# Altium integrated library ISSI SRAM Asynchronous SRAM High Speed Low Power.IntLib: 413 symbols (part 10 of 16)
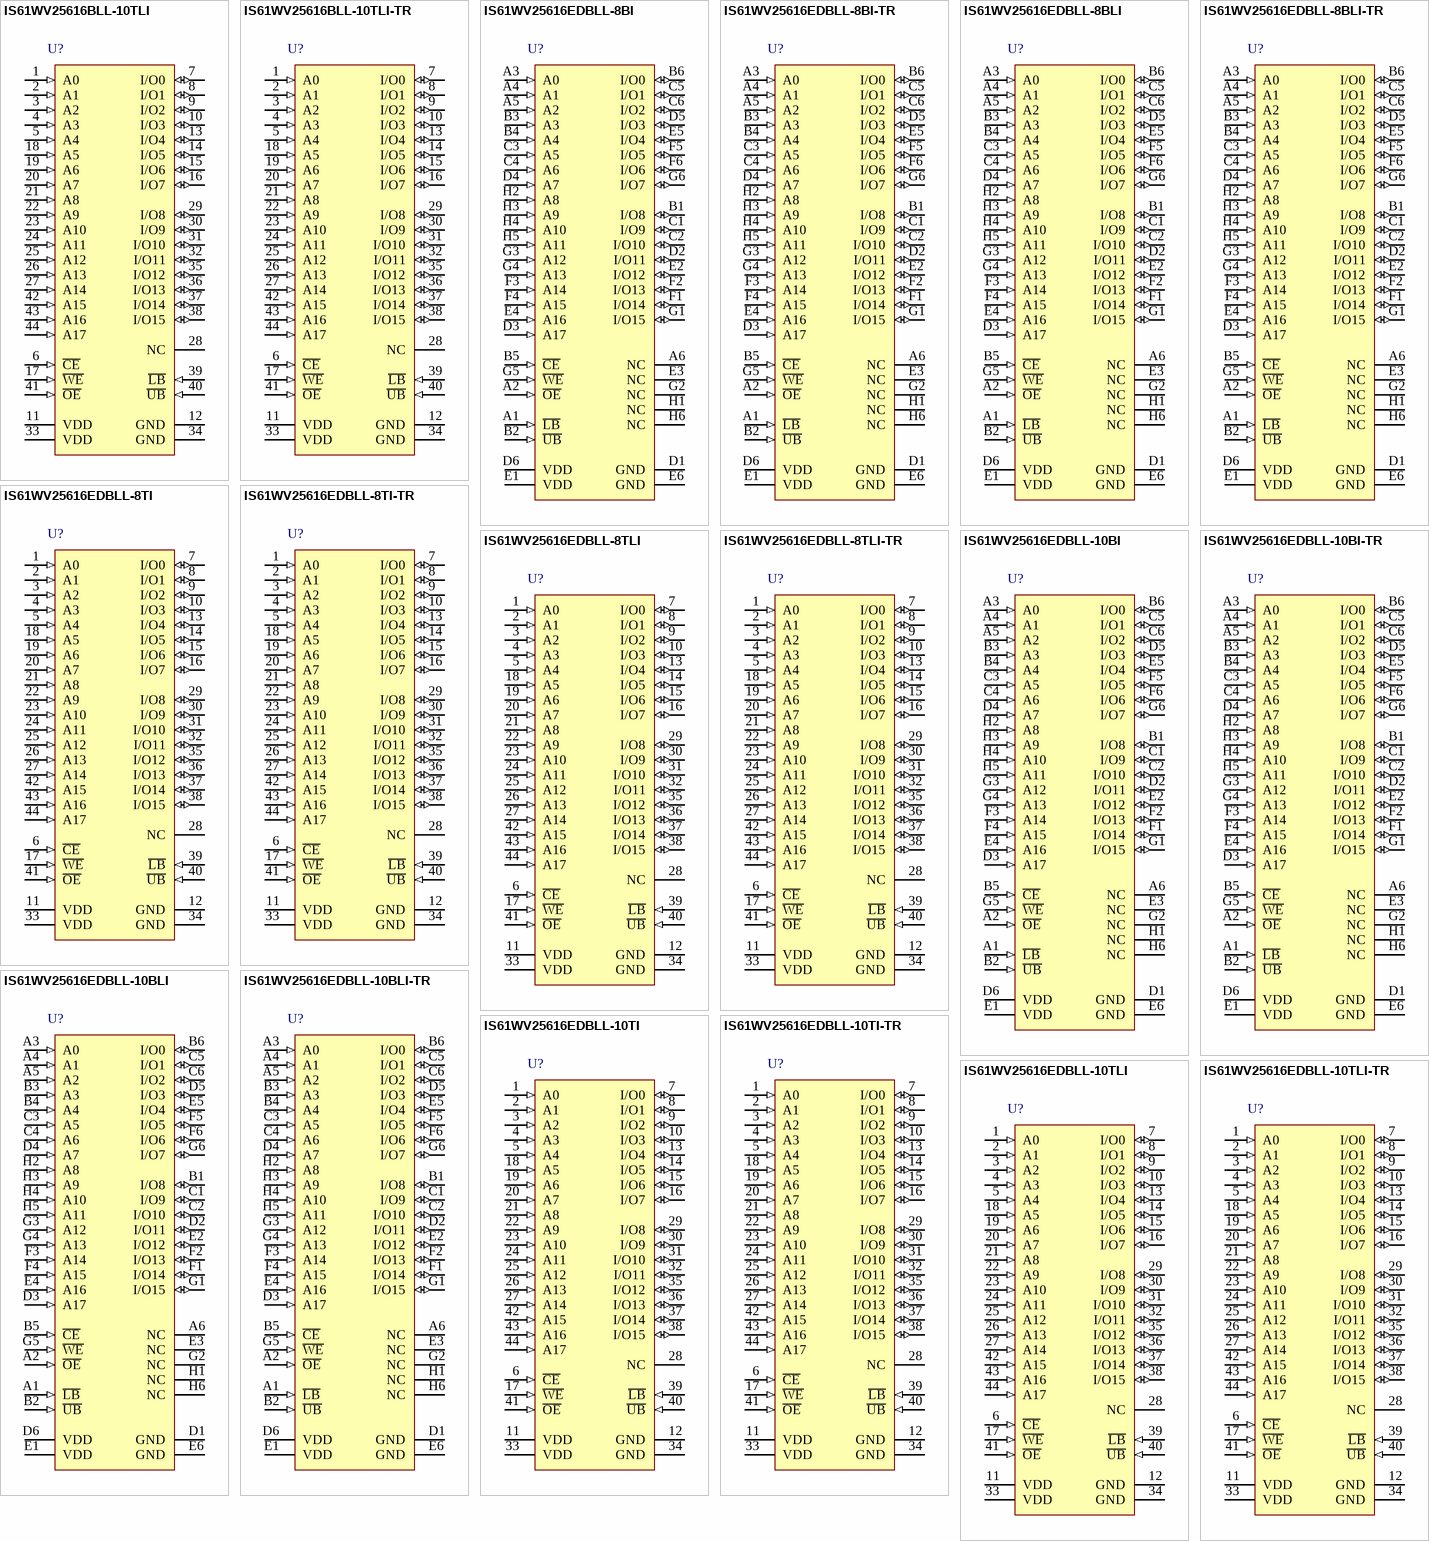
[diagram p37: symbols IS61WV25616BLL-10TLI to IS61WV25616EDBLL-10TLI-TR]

## IS61WV25616EDBLL-8BLI-TR
designator U?
4 M High Speed Asynchronous CMOS SRAM with ECC, 256 K x 16, -40 to 85 degC, 48-Pin BGA (TF-BGA-48), Pb-Free; Manufacturer: Integrated Silicon Solution Inc (ISSI); PartNumber: IS61WV25616EDBLL-8BLI-TR; Density: 4M; Packing: Tape & Reel; Speed (ns): 8
footprint ISSI-TF-BGA-48-6000X8000DE (BGA, 48-Balls, Body 8x6mm, Pitch 0.75mm)
pins: A1 ~{LB} (in) "Lower-byte Control (I/O0-I/O7)", A2 ~{OE} (in) "Output Enable Input", A3 A0 (in) "Address Input", A4 A1 (in) "Address Input", A5 A2 (in) "Address Input", A6 NC "No Connection", B1 I/O8 (io) "Data Input/Output", B2 ~{UB} (in) "Upper-byte Control (I/O8-I/O15)", B3 A3 (in) "Address Input", B4 A4 (in) "Address Input", B5 ~{CE} (in) "Chip Enable Input", B6 I/O0 (io) "Data Input/Output", C1 I/O9 (io) "Data Input/Output", C2 I/O10 (io) "Data Input/Output", C3 A5 (in) "Address Input", C4 A6 (in) "Address Input", C5 I/O1 (io) "Data Input/Output", C6 I/O2 (io) "Data Input/Output", D1 GND (power) "Ground", D2 I/O11 (io) "Data Input/Output", D3 A17 (in) "Address Input", D4 A7 (in) "Address Input", D5 I/O3 (io) "Data Input/Output", D6 VDD (power) "Power", E1 VDD (power) "Power", E2 I/O12 (io) "Data Input/Output", E3 NC "No Connection", E4 A16 (in) "Address Input", E5 I/O4 (io) "Data Input/Output", E6 GND (power) "Ground", F1 I/O14 (io) "Data Input/Output", F2 I/O13 (io) "Data Input/Output", F3 A14 (in) "Address Input", F4 A15 (in) "Address Input", F5 I/O5 (io) "Data Input/Output", F6 I/O6 (io) "Data Input/Output", G1 I/O15 (io) "Data Input/Output", G2 NC "No Connection", G3 A12 (in) "Address Input", G4 A13 (in) "Address Input", G5 ~{WE} (in) "Write Enable Input", G6 I/O7 (io) "Data Input/Output", H1 NC "No Connection", H2 A8 (in) "Address Input", H3 A9 (in) "Address Input", H4 A10 (in) "Address Input", H5 A11 (in) "Address Input", H6 NC "No Connection"

## IS61WV25616EDBLL-8TI
designator U?
4 M High Speed Asynchronous CMOS SRAM with ECC, 256 K x 16, -40 to 85 degC, 44-Pin SOP (TSOP-2-44); Manufacturer: Integrated Silicon Solution Inc (ISSI); PartNumber: IS61WV25616EDBLL-8TI; Density: 4M; Packing: Tray / Tube; Speed (ns): 8
footprint ISSI-TSOP-2-44_N (SOP, 44-Leads, Body 18.5x10.3mm, Pitch 0.8mm, IPC Medium Density)
pins: 1 A0 (in) "Address Input", 2 A1 (in) "Address Input", 3 A2 (in) "Address Input", 4 A3 (in) "Address Input", 5 A4 (in) "Address Input", 6 ~{CE} (in) "Chip Enable Input", 7 I/O0 (io) "Data Input/Output", 8 I/O1 (io) "Data Input/Output", 9 I/O2 (io) "Data Input/Output", 10 I/O3 (io) "Data Input/Output", 11 VDD (power) "Power", 12 GND (power) "Ground", 13 I/O4 (io) "Data Input/Output", 14 I/O5 (io) "Data Input/Output", 15 I/O6 (io) "Data Input/Output", 16 I/O7 (io) "Data Input/Output", 17 ~{WE} (in) "Write Enable Input", 18 A5 (in) "Address Input", 19 A6 (in) "Address Input", 20 A7 (in) "Address Input", 21 A8 (in) "Address Input", 22 A9 (in) "Address Input", 23 A10 (in) "Address Input", 24 A11 (in) "Address Input", 25 A12 (in) "Address Input", 26 A13 (in) "Address Input", 27 A14 (in) "Address Input", 28 NC "No Connection", 29 I/O8 (io) "Data Input/Output", 30 I/O9 (io) "Data Input/Output", 31 I/O10 (io) "Data Input/Output", 32 I/O11 (io) "Data Input/Output", 33 VDD (power) "Power", 34 GND (power) "Ground", 35 I/O12 (io) "Data Input/Output", 36 I/O13 (io) "Data Input/Output", 37 I/O14 (io) "Data Input/Output", 38 I/O15 (io) "Data Input/Output", 39 ~{LB} (in) "Lower-byte Control (I/O0-I/O7)", 40 ~{UB} (in) "Upper-byte Control (I/O8-I/O15)", 41 ~{OE} (in) "Output Enable Input", 42 A15 (in) "Address Input", 43 A16 (in) "Address Input", 44 A17 (in) "Address Input"

## IS61WV25616EDBLL-8TI-TR
designator U?
4 M High Speed Asynchronous CMOS SRAM with ECC, 256 K x 16, -40 to 85 degC, 44-Pin SOP (TSOP-2-44); Manufacturer: Integrated Silicon Solution Inc (ISSI); PartNumber: IS61WV25616EDBLL-8TI-TR; Density: 4M; Packing: Tape & Reel; Speed (ns): 8
footprint ISSI-TSOP-2-44_N (SOP, 44-Leads, Body 18.5x10.3mm, Pitch 0.8mm, IPC Medium Density)
pins: 1 A0 (in) "Address Input", 2 A1 (in) "Address Input", 3 A2 (in) "Address Input", 4 A3 (in) "Address Input", 5 A4 (in) "Address Input", 6 ~{CE} (in) "Chip Enable Input", 7 I/O0 (io) "Data Input/Output", 8 I/O1 (io) "Data Input/Output", 9 I/O2 (io) "Data Input/Output", 10 I/O3 (io) "Data Input/Output", 11 VDD (power) "Power", 12 GND (power) "Ground", 13 I/O4 (io) "Data Input/Output", 14 I/O5 (io) "Data Input/Output", 15 I/O6 (io) "Data Input/Output", 16 I/O7 (io) "Data Input/Output", 17 ~{WE} (in) "Write Enable Input", 18 A5 (in) "Address Input", 19 A6 (in) "Address Input", 20 A7 (in) "Address Input", 21 A8 (in) "Address Input", 22 A9 (in) "Address Input", 23 A10 (in) "Address Input", 24 A11 (in) "Address Input", 25 A12 (in) "Address Input", 26 A13 (in) "Address Input", 27 A14 (in) "Address Input", 28 NC "No Connection", 29 I/O8 (io) "Data Input/Output", 30 I/O9 (io) "Data Input/Output", 31 I/O10 (io) "Data Input/Output", 32 I/O11 (io) "Data Input/Output", 33 VDD (power) "Power", 34 GND (power) "Ground", 35 I/O12 (io) "Data Input/Output", 36 I/O13 (io) "Data Input/Output", 37 I/O14 (io) "Data Input/Output", 38 I/O15 (io) "Data Input/Output", 39 ~{LB} (in) "Lower-byte Control (I/O0-I/O7)", 40 ~{UB} (in) "Upper-byte Control (I/O8-I/O15)", 41 ~{OE} (in) "Output Enable Input", 42 A15 (in) "Address Input", 43 A16 (in) "Address Input", 44 A17 (in) "Address Input"

## IS61WV25616EDBLL-8TLI
designator U?
4 M High Speed Asynchronous CMOS SRAM with ECC, 256 K x 16, -40 to 85 degC, 44-Pin SOP (TSOP-2-44), Pb-Free; Manufacturer: Integrated Silicon Solution Inc (ISSI); PartNumber: IS61WV25616EDBLL-8TLI; Density: 4M; Packing: Tray / Tube; Speed (ns): 8
footprint ISSI-TSOP-2-44_N (SOP, 44-Leads, Body 18.5x10.3mm, Pitch 0.8mm, IPC Medium Density)
pins: 1 A0 (in) "Address Input", 2 A1 (in) "Address Input", 3 A2 (in) "Address Input", 4 A3 (in) "Address Input", 5 A4 (in) "Address Input", 6 ~{CE} (in) "Chip Enable Input", 7 I/O0 (io) "Data Input/Output", 8 I/O1 (io) "Data Input/Output", 9 I/O2 (io) "Data Input/Output", 10 I/O3 (io) "Data Input/Output", 11 VDD (power) "Power", 12 GND (power) "Ground", 13 I/O4 (io) "Data Input/Output", 14 I/O5 (io) "Data Input/Output", 15 I/O6 (io) "Data Input/Output", 16 I/O7 (io) "Data Input/Output", 17 ~{WE} (in) "Write Enable Input", 18 A5 (in) "Address Input", 19 A6 (in) "Address Input", 20 A7 (in) "Address Input", 21 A8 (in) "Address Input", 22 A9 (in) "Address Input", 23 A10 (in) "Address Input", 24 A11 (in) "Address Input", 25 A12 (in) "Address Input", 26 A13 (in) "Address Input", 27 A14 (in) "Address Input", 28 NC "No Connection", 29 I/O8 (io) "Data Input/Output", 30 I/O9 (io) "Data Input/Output", 31 I/O10 (io) "Data Input/Output", 32 I/O11 (io) "Data Input/Output", 33 VDD (power) "Power", 34 GND (power) "Ground", 35 I/O12 (io) "Data Input/Output", 36 I/O13 (io) "Data Input/Output", 37 I/O14 (io) "Data Input/Output", 38 I/O15 (io) "Data Input/Output", 39 ~{LB} (in) "Lower-byte Control (I/O0-I/O7)", 40 ~{UB} (in) "Upper-byte Control (I/O8-I/O15)", 41 ~{OE} (in) "Output Enable Input", 42 A15 (in) "Address Input", 43 A16 (in) "Address Input", 44 A17 (in) "Address Input"

## IS61WV25616EDBLL-8TLI-TR
designator U?
4 M High Speed Asynchronous CMOS SRAM with ECC, 256 K x 16, -40 to 85 degC, 44-Pin SOP (TSOP-2-44), Pb-Free; Manufacturer: Integrated Silicon Solution Inc (ISSI); PartNumber: IS61WV25616EDBLL-8TLI-TR; Density: 4M; Packing: Tape & Reel; Speed (ns): 8
footprint ISSI-TSOP-2-44_N (SOP, 44-Leads, Body 18.5x10.3mm, Pitch 0.8mm, IPC Medium Density)
pins: 1 A0 (in) "Address Input", 2 A1 (in) "Address Input", 3 A2 (in) "Address Input", 4 A3 (in) "Address Input", 5 A4 (in) "Address Input", 6 ~{CE} (in) "Chip Enable Input", 7 I/O0 (io) "Data Input/Output", 8 I/O1 (io) "Data Input/Output", 9 I/O2 (io) "Data Input/Output", 10 I/O3 (io) "Data Input/Output", 11 VDD (power) "Power", 12 GND (power) "Ground", 13 I/O4 (io) "Data Input/Output", 14 I/O5 (io) "Data Input/Output", 15 I/O6 (io) "Data Input/Output", 16 I/O7 (io) "Data Input/Output", 17 ~{WE} (in) "Write Enable Input", 18 A5 (in) "Address Input", 19 A6 (in) "Address Input", 20 A7 (in) "Address Input", 21 A8 (in) "Address Input", 22 A9 (in) "Address Input", 23 A10 (in) "Address Input", 24 A11 (in) "Address Input", 25 A12 (in) "Address Input", 26 A13 (in) "Address Input", 27 A14 (in) "Address Input", 28 NC "No Connection", 29 I/O8 (io) "Data Input/Output", 30 I/O9 (io) "Data Input/Output", 31 I/O10 (io) "Data Input/Output", 32 I/O11 (io) "Data Input/Output", 33 VDD (power) "Power", 34 GND (power) "Ground", 35 I/O12 (io) "Data Input/Output", 36 I/O13 (io) "Data Input/Output", 37 I/O14 (io) "Data Input/Output", 38 I/O15 (io) "Data Input/Output", 39 ~{LB} (in) "Lower-byte Control (I/O0-I/O7)", 40 ~{UB} (in) "Upper-byte Control (I/O8-I/O15)", 41 ~{OE} (in) "Output Enable Input", 42 A15 (in) "Address Input", 43 A16 (in) "Address Input", 44 A17 (in) "Address Input"

## IS61WV25616EDBLL-10BI
designator U?
4 M High Speed Asynchronous CMOS SRAM with ECC, 256 K x 16, -40 to 85 degC, 48-Pin BGA (TF-BGA-48); Manufacturer: Integrated Silicon Solution Inc (ISSI); PartNumber: IS61WV25616EDBLL-10BI; Density: 4M; Packing: Tray / Tube; Speed (ns): 10
footprint ISSI-TF-BGA-48-6000X8000DE (BGA, 48-Balls, Body 8x6mm, Pitch 0.75mm)
pins: A1 ~{LB} (in) "Lower-byte Control (I/O0-I/O7)", A2 ~{OE} (in) "Output Enable Input", A3 A0 (in) "Address Input", A4 A1 (in) "Address Input", A5 A2 (in) "Address Input", A6 NC "No Connection", B1 I/O8 (io) "Data Input/Output", B2 ~{UB} (in) "Upper-byte Control (I/O8-I/O15)", B3 A3 (in) "Address Input", B4 A4 (in) "Address Input", B5 ~{CE} (in) "Chip Enable Input", B6 I/O0 (io) "Data Input/Output", C1 I/O9 (io) "Data Input/Output", C2 I/O10 (io) "Data Input/Output", C3 A5 (in) "Address Input", C4 A6 (in) "Address Input", C5 I/O1 (io) "Data Input/Output", C6 I/O2 (io) "Data Input/Output", D1 GND (power) "Ground", D2 I/O11 (io) "Data Input/Output", D3 A17 (in) "Address Input", D4 A7 (in) "Address Input", D5 I/O3 (io) "Data Input/Output", D6 VDD (power) "Power", E1 VDD (power) "Power", E2 I/O12 (io) "Data Input/Output", E3 NC "No Connection", E4 A16 (in) "Address Input", E5 I/O4 (io) "Data Input/Output", E6 GND (power) "Ground", F1 I/O14 (io) "Data Input/Output", F2 I/O13 (io) "Data Input/Output", F3 A14 (in) "Address Input", F4 A15 (in) "Address Input", F5 I/O5 (io) "Data Input/Output", F6 I/O6 (io) "Data Input/Output", G1 I/O15 (io) "Data Input/Output", G2 NC "No Connection", G3 A12 (in) "Address Input", G4 A13 (in) "Address Input", G5 ~{WE} (in) "Write Enable Input", G6 I/O7 (io) "Data Input/Output", H1 NC "No Connection", H2 A8 (in) "Address Input", H3 A9 (in) "Address Input", H4 A10 (in) "Address Input", H5 A11 (in) "Address Input", H6 NC "No Connection"

## IS61WV25616EDBLL-10BI-TR
designator U?
4 M High Speed Asynchronous CMOS SRAM with ECC, 256 K x 16, -40 to 85 degC, 48-Pin BGA (TF-BGA-48); Manufacturer: Integrated Silicon Solution Inc (ISSI); PartNumber: IS61WV25616EDBLL-10BI-TR; Density: 4M; Packing: Tape & Reel; Speed (ns): 10
footprint ISSI-TF-BGA-48-6000X8000DE (BGA, 48-Balls, Body 8x6mm, Pitch 0.75mm)
pins: A1 ~{LB} (in) "Lower-byte Control (I/O0-I/O7)", A2 ~{OE} (in) "Output Enable Input", A3 A0 (in) "Address Input", A4 A1 (in) "Address Input", A5 A2 (in) "Address Input", A6 NC "No Connection", B1 I/O8 (io) "Data Input/Output", B2 ~{UB} (in) "Upper-byte Control (I/O8-I/O15)", B3 A3 (in) "Address Input", B4 A4 (in) "Address Input", B5 ~{CE} (in) "Chip Enable Input", B6 I/O0 (io) "Data Input/Output", C1 I/O9 (io) "Data Input/Output", C2 I/O10 (io) "Data Input/Output", C3 A5 (in) "Address Input", C4 A6 (in) "Address Input", C5 I/O1 (io) "Data Input/Output", C6 I/O2 (io) "Data Input/Output", D1 GND (power) "Ground", D2 I/O11 (io) "Data Input/Output", D3 A17 (in) "Address Input", D4 A7 (in) "Address Input", D5 I/O3 (io) "Data Input/Output", D6 VDD (power) "Power", E1 VDD (power) "Power", E2 I/O12 (io) "Data Input/Output", E3 NC "No Connection", E4 A16 (in) "Address Input", E5 I/O4 (io) "Data Input/Output", E6 GND (power) "Ground", F1 I/O14 (io) "Data Input/Output", F2 I/O13 (io) "Data Input/Output", F3 A14 (in) "Address Input", F4 A15 (in) "Address Input", F5 I/O5 (io) "Data Input/Output", F6 I/O6 (io) "Data Input/Output", G1 I/O15 (io) "Data Input/Output", G2 NC "No Connection", G3 A12 (in) "Address Input", G4 A13 (in) "Address Input", G5 ~{WE} (in) "Write Enable Input", G6 I/O7 (io) "Data Input/Output", H1 NC "No Connection", H2 A8 (in) "Address Input", H3 A9 (in) "Address Input", H4 A10 (in) "Address Input", H5 A11 (in) "Address Input", H6 NC "No Connection"

## IS61WV25616EDBLL-10BLI
designator U?
4 M High Speed Asynchronous CMOS SRAM with ECC, 256 K x 16, -40 to 85 degC, 48-Pin BGA (TF-BGA-48), Pb-Free; Manufacturer: Integrated Silicon Solution Inc (ISSI); PartNumber: IS61WV25616EDBLL-10BLI; Density: 4M; Packing: Tray / Tube; Speed (ns): 10
footprint ISSI-TF-BGA-48-6000X8000DE (BGA, 48-Balls, Body 8x6mm, Pitch 0.75mm)
pins: A1 ~{LB} (in) "Lower-byte Control (I/O0-I/O7)", A2 ~{OE} (in) "Output Enable Input", A3 A0 (in) "Address Input", A4 A1 (in) "Address Input", A5 A2 (in) "Address Input", A6 NC "No Connection", B1 I/O8 (io) "Data Input/Output", B2 ~{UB} (in) "Upper-byte Control (I/O8-I/O15)", B3 A3 (in) "Address Input", B4 A4 (in) "Address Input", B5 ~{CE} (in) "Chip Enable Input", B6 I/O0 (io) "Data Input/Output", C1 I/O9 (io) "Data Input/Output", C2 I/O10 (io) "Data Input/Output", C3 A5 (in) "Address Input", C4 A6 (in) "Address Input", C5 I/O1 (io) "Data Input/Output", C6 I/O2 (io) "Data Input/Output", D1 GND (power) "Ground", D2 I/O11 (io) "Data Input/Output", D3 A17 (in) "Address Input", D4 A7 (in) "Address Input", D5 I/O3 (io) "Data Input/Output", D6 VDD (power) "Power", E1 VDD (power) "Power", E2 I/O12 (io) "Data Input/Output", E3 NC "No Connection", E4 A16 (in) "Address Input", E5 I/O4 (io) "Data Input/Output", E6 GND (power) "Ground", F1 I/O14 (io) "Data Input/Output", F2 I/O13 (io) "Data Input/Output", F3 A14 (in) "Address Input", F4 A15 (in) "Address Input", F5 I/O5 (io) "Data Input/Output", F6 I/O6 (io) "Data Input/Output", G1 I/O15 (io) "Data Input/Output", G2 NC "No Connection", G3 A12 (in) "Address Input", G4 A13 (in) "Address Input", G5 ~{WE} (in) "Write Enable Input", G6 I/O7 (io) "Data Input/Output", H1 NC "No Connection", H2 A8 (in) "Address Input", H3 A9 (in) "Address Input", H4 A10 (in) "Address Input", H5 A11 (in) "Address Input", H6 NC "No Connection"

## IS61WV25616EDBLL-10BLI-TR
designator U?
4 M High Speed Asynchronous CMOS SRAM with ECC, 256 K x 16, -40 to 85 degC, 48-Pin BGA (TF-BGA-48), Pb-Free; Manufacturer: Integrated Silicon Solution Inc (ISSI); PartNumber: IS61WV25616EDBLL-10BLI-TR; Density: 4M; Packing: Tape & Reel; Speed (ns): 10
footprint ISSI-TF-BGA-48-6000X8000DE (BGA, 48-Balls, Body 8x6mm, Pitch 0.75mm)
pins: A1 ~{LB} (in) "Lower-byte Control (I/O0-I/O7)", A2 ~{OE} (in) "Output Enable Input", A3 A0 (in) "Address Input", A4 A1 (in) "Address Input", A5 A2 (in) "Address Input", A6 NC "No Connection", B1 I/O8 (io) "Data Input/Output", B2 ~{UB} (in) "Upper-byte Control (I/O8-I/O15)", B3 A3 (in) "Address Input", B4 A4 (in) "Address Input", B5 ~{CE} (in) "Chip Enable Input", B6 I/O0 (io) "Data Input/Output", C1 I/O9 (io) "Data Input/Output", C2 I/O10 (io) "Data Input/Output", C3 A5 (in) "Address Input", C4 A6 (in) "Address Input", C5 I/O1 (io) "Data Input/Output", C6 I/O2 (io) "Data Input/Output", D1 GND (power) "Ground", D2 I/O11 (io) "Data Input/Output", D3 A17 (in) "Address Input", D4 A7 (in) "Address Input", D5 I/O3 (io) "Data Input/Output", D6 VDD (power) "Power", E1 VDD (power) "Power", E2 I/O12 (io) "Data Input/Output", E3 NC "No Connection", E4 A16 (in) "Address Input", E5 I/O4 (io) "Data Input/Output", E6 GND (power) "Ground", F1 I/O14 (io) "Data Input/Output", F2 I/O13 (io) "Data Input/Output", F3 A14 (in) "Address Input", F4 A15 (in) "Address Input", F5 I/O5 (io) "Data Input/Output", F6 I/O6 (io) "Data Input/Output", G1 I/O15 (io) "Data Input/Output", G2 NC "No Connection", G3 A12 (in) "Address Input", G4 A13 (in) "Address Input", G5 ~{WE} (in) "Write Enable Input", G6 I/O7 (io) "Data Input/Output", H1 NC "No Connection", H2 A8 (in) "Address Input", H3 A9 (in) "Address Input", H4 A10 (in) "Address Input", H5 A11 (in) "Address Input", H6 NC "No Connection"

## IS61WV25616EDBLL-10TI
designator U?
4 M High Speed Asynchronous CMOS SRAM with ECC, 256 K x 16, -40 to 85 degC, 44-Pin SOP (TSOP-2-44); Manufacturer: Integrated Silicon Solution Inc (ISSI); PartNumber: IS61WV25616EDBLL-10TI; Density: 4M; Packing: Tray / Tube; Speed (ns): 10
footprint ISSI-TSOP-2-44_N (SOP, 44-Leads, Body 18.5x10.3mm, Pitch 0.8mm, IPC Medium Density)
pins: 1 A0 (in) "Address Input", 2 A1 (in) "Address Input", 3 A2 (in) "Address Input", 4 A3 (in) "Address Input", 5 A4 (in) "Address Input", 6 ~{CE} (in) "Chip Enable Input", 7 I/O0 (io) "Data Input/Output", 8 I/O1 (io) "Data Input/Output", 9 I/O2 (io) "Data Input/Output", 10 I/O3 (io) "Data Input/Output", 11 VDD (power) "Power", 12 GND (power) "Ground", 13 I/O4 (io) "Data Input/Output", 14 I/O5 (io) "Data Input/Output", 15 I/O6 (io) "Data Input/Output", 16 I/O7 (io) "Data Input/Output", 17 ~{WE} (in) "Write Enable Input", 18 A5 (in) "Address Input", 19 A6 (in) "Address Input", 20 A7 (in) "Address Input", 21 A8 (in) "Address Input", 22 A9 (in) "Address Input", 23 A10 (in) "Address Input", 24 A11 (in) "Address Input", 25 A12 (in) "Address Input", 26 A13 (in) "Address Input", 27 A14 (in) "Address Input", 28 NC "No Connection", 29 I/O8 (io) "Data Input/Output", 30 I/O9 (io) "Data Input/Output", 31 I/O10 (io) "Data Input/Output", 32 I/O11 (io) "Data Input/Output", 33 VDD (power) "Power", 34 GND (power) "Ground", 35 I/O12 (io) "Data Input/Output", 36 I/O13 (io) "Data Input/Output", 37 I/O14 (io) "Data Input/Output", 38 I/O15 (io) "Data Input/Output", 39 ~{LB} (in) "Lower-byte Control (I/O0-I/O7)", 40 ~{UB} (in) "Upper-byte Control (I/O8-I/O15)", 41 ~{OE} (in) "Output Enable Input", 42 A15 (in) "Address Input", 43 A16 (in) "Address Input", 44 A17 (in) "Address Input"

## IS61WV25616EDBLL-10TI-TR
designator U?
4 M High Speed Asynchronous CMOS SRAM with ECC, 256 K x 16, -40 to 85 degC, 44-Pin SOP (TSOP-2-44); Manufacturer: Integrated Silicon Solution Inc (ISSI); PartNumber: IS61WV25616EDBLL-10TI-TR; Density: 4M; Packing: Tape & Reel; Speed (ns): 10
footprint ISSI-TSOP-2-44_N (SOP, 44-Leads, Body 18.5x10.3mm, Pitch 0.8mm, IPC Medium Density)
pins: 1 A0 (in) "Address Input", 2 A1 (in) "Address Input", 3 A2 (in) "Address Input", 4 A3 (in) "Address Input", 5 A4 (in) "Address Input", 6 ~{CE} (in) "Chip Enable Input", 7 I/O0 (io) "Data Input/Output", 8 I/O1 (io) "Data Input/Output", 9 I/O2 (io) "Data Input/Output", 10 I/O3 (io) "Data Input/Output", 11 VDD (power) "Power", 12 GND (power) "Ground", 13 I/O4 (io) "Data Input/Output", 14 I/O5 (io) "Data Input/Output", 15 I/O6 (io) "Data Input/Output", 16 I/O7 (io) "Data Input/Output", 17 ~{WE} (in) "Write Enable Input", 18 A5 (in) "Address Input", 19 A6 (in) "Address Input", 20 A7 (in) "Address Input", 21 A8 (in) "Address Input", 22 A9 (in) "Address Input", 23 A10 (in) "Address Input", 24 A11 (in) "Address Input", 25 A12 (in) "Address Input", 26 A13 (in) "Address Input", 27 A14 (in) "Address Input", 28 NC "No Connection", 29 I/O8 (io) "Data Input/Output", 30 I/O9 (io) "Data Input/Output", 31 I/O10 (io) "Data Input/Output", 32 I/O11 (io) "Data Input/Output", 33 VDD (power) "Power", 34 GND (power) "Ground", 35 I/O12 (io) "Data Input/Output", 36 I/O13 (io) "Data Input/Output", 37 I/O14 (io) "Data Input/Output", 38 I/O15 (io) "Data Input/Output", 39 ~{LB} (in) "Lower-byte Control (I/O0-I/O7)", 40 ~{UB} (in) "Upper-byte Control (I/O8-I/O15)", 41 ~{OE} (in) "Output Enable Input", 42 A15 (in) "Address Input", 43 A16 (in) "Address Input", 44 A17 (in) "Address Input"

## IS61WV25616EDBLL-10TLI
designator U?
4 M High Speed Asynchronous CMOS SRAM with ECC, 256 K x 16, -40 to 85 degC, 44-Pin SOP (TSOP-2-44), Pb-Free; Manufacturer: Integrated Silicon Solution Inc (ISSI); PartNumber: IS61WV25616EDBLL-10TLI; Density: 4M; Packing: Tray / Tube; Speed (ns): 10
footprint ISSI-TSOP-2-44_N (SOP, 44-Leads, Body 18.5x10.3mm, Pitch 0.8mm, IPC Medium Density)
pins: 1 A0 (in) "Address Input", 2 A1 (in) "Address Input", 3 A2 (in) "Address Input", 4 A3 (in) "Address Input", 5 A4 (in) "Address Input", 6 ~{CE} (in) "Chip Enable Input", 7 I/O0 (io) "Data Input/Output", 8 I/O1 (io) "Data Input/Output", 9 I/O2 (io) "Data Input/Output", 10 I/O3 (io) "Data Input/Output", 11 VDD (power) "Power", 12 GND (power) "Ground", 13 I/O4 (io) "Data Input/Output", 14 I/O5 (io) "Data Input/Output", 15 I/O6 (io) "Data Input/Output", 16 I/O7 (io) "Data Input/Output", 17 ~{WE} (in) "Write Enable Input", 18 A5 (in) "Address Input", 19 A6 (in) "Address Input", 20 A7 (in) "Address Input", 21 A8 (in) "Address Input", 22 A9 (in) "Address Input", 23 A10 (in) "Address Input", 24 A11 (in) "Address Input", 25 A12 (in) "Address Input", 26 A13 (in) "Address Input", 27 A14 (in) "Address Input", 28 NC "No Connection", 29 I/O8 (io) "Data Input/Output", 30 I/O9 (io) "Data Input/Output", 31 I/O10 (io) "Data Input/Output", 32 I/O11 (io) "Data Input/Output", 33 VDD (power) "Power", 34 GND (power) "Ground", 35 I/O12 (io) "Data Input/Output", 36 I/O13 (io) "Data Input/Output", 37 I/O14 (io) "Data Input/Output", 38 I/O15 (io) "Data Input/Output", 39 ~{LB} (in) "Lower-byte Control (I/O0-I/O7)", 40 ~{UB} (in) "Upper-byte Control (I/O8-I/O15)", 41 ~{OE} (in) "Output Enable Input", 42 A15 (in) "Address Input", 43 A16 (in) "Address Input", 44 A17 (in) "Address Input"

## IS61WV25616EDBLL-10TLI-TR
designator U?
4 M High Speed Asynchronous CMOS SRAM with ECC, 256 K x 16, -40 to 85 degC, 44-Pin SOP (TSOP-2-44), Pb-Free; Manufacturer: Integrated Silicon Solution Inc (ISSI); PartNumber: IS61WV25616EDBLL-10TLI-TR; Density: 4M; Packing: Tape & Reel; Speed (ns): 10
footprint ISSI-TSOP-2-44_N (SOP, 44-Leads, Body 18.5x10.3mm, Pitch 0.8mm, IPC Medium Density)
pins: 1 A0 (in) "Address Input", 2 A1 (in) "Address Input", 3 A2 (in) "Address Input", 4 A3 (in) "Address Input", 5 A4 (in) "Address Input", 6 ~{CE} (in) "Chip Enable Input", 7 I/O0 (io) "Data Input/Output", 8 I/O1 (io) "Data Input/Output", 9 I/O2 (io) "Data Input/Output", 10 I/O3 (io) "Data Input/Output", 11 VDD (power) "Power", 12 GND (power) "Ground", 13 I/O4 (io) "Data Input/Output", 14 I/O5 (io) "Data Input/Output", 15 I/O6 (io) "Data Input/Output", 16 I/O7 (io) "Data Input/Output", 17 ~{WE} (in) "Write Enable Input", 18 A5 (in) "Address Input", 19 A6 (in) "Address Input", 20 A7 (in) "Address Input", 21 A8 (in) "Address Input", 22 A9 (in) "Address Input", 23 A10 (in) "Address Input", 24 A11 (in) "Address Input", 25 A12 (in) "Address Input", 26 A13 (in) "Address Input", 27 A14 (in) "Address Input", 28 NC "No Connection", 29 I/O8 (io) "Data Input/Output", 30 I/O9 (io) "Data Input/Output", 31 I/O10 (io) "Data Input/Output", 32 I/O11 (io) "Data Input/Output", 33 VDD (power) "Power", 34 GND (power) "Ground", 35 I/O12 (io) "Data Input/Output", 36 I/O13 (io) "Data Input/Output", 37 I/O14 (io) "Data Input/Output", 38 I/O15 (io) "Data Input/Output", 39 ~{LB} (in) "Lower-byte Control (I/O0-I/O7)", 40 ~{UB} (in) "Upper-byte Control (I/O8-I/O15)", 41 ~{OE} (in) "Output Enable Input", 42 A15 (in) "Address Input", 43 A16 (in) "Address Input", 44 A17 (in) "Address Input"

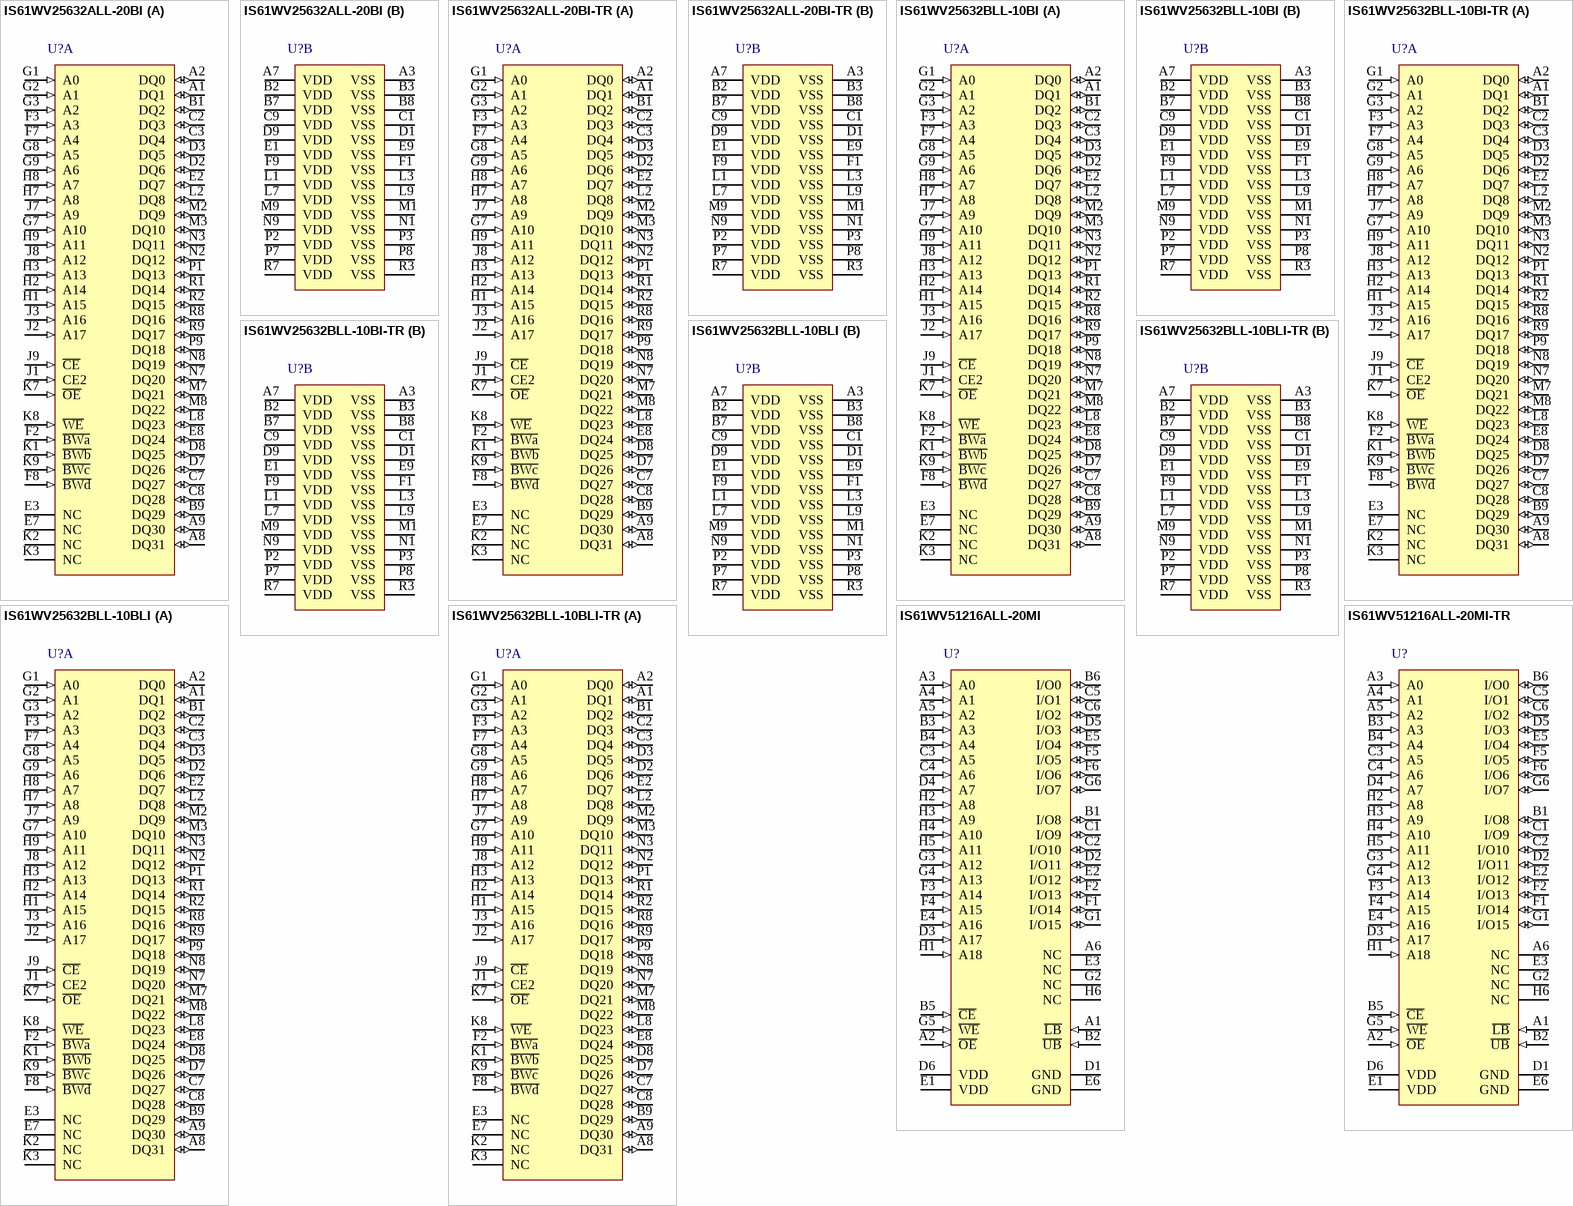
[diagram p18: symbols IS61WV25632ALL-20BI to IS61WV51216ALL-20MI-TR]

## IS61WV25632ALL-20BI
designator U?
8 M High Speed Asynchronous CMOS SRAM with 3.3 V Supply, 256 K x 32, -40 to 85 degC, 90-Pin BGA (TF-BGA-90); Manufacturer: Integrated Silicon Solution Inc (ISSI); PartNumber: IS61WV25632ALL-20BI; Density: 8M; Packing: Tray / Tube; Speed (ns): 20
footprint ISSI-TF-BGA-90-8000X13000DE (BGA, 90-Balls, Body 13x8mm, Pitch 0.8mm)
part A pins: A1 DQ1 (io) "Data I/O", A2 DQ0 (io) "Data I/O", A8 DQ31 (io) "Data I/O", A9 DQ30 (io) "Data I/O", B1 DQ2 (io) "Data I/O", B9 DQ29 (io) "Data I/O", C2 DQ3 (io) "Data I/O", C3 DQ4 (io) "Data I/O", C7 DQ27 (io) "Data I/O", C8 DQ28 (io) "Data I/O", D2 DQ6 (io) "Data I/O", D3 DQ5 (io) "Data I/O", D7 DQ26 (io) "Data I/O", D8 DQ25 (io) "Data I/O", E2 DQ7 (io) "Data I/O", E3 NC "No Connection", E7 NC "No Connection", E8 DQ24 (io) "Data I/O", F2 ~{BWa} (in) "Byte Write Control", F3 A3 (in) "Address Inputs", F7 A4 (in) "Address Inputs", F8 ~{BWd} (in) "Byte Write Control", G1 A0 (in) "Address Inputs", G2 A1 (in) "Address Inputs", G3 A2 (in) "Address Inputs", G7 A10 (in) "Address Inputs", G8 A5 (in) "Address Inputs", G9 A6 (in) "Address Inputs", H1 A15 (in) "Address Inputs", H2 A14 (in) "Address Inputs", H3 A13 (in) "Address Inputs", H7 A8 (in) "Address Inputs", H8 A7 (in) "Address Inputs", H9 A11 (in) "Address Inputs", J1 CE2 (in) "Chip Enable Input", J2 A17 (in) "Address Inputs", J3 A16 (in) "Address Inputs", J7 A9 (in) "Address Inputs", J8 A12 (in) "Address Inputs", J9 ~{CE} (in) "Chip Enable Input", K1 ~{BWb} (in) "Byte Write Control", K2 NC "No Connection", K3 NC "No Connection", K7 ~{OE} (in) "Output Enable Input", K8 ~{WE} (in) "Write Enable Input", K9 ~{BWc} (in) "Byte Write Control", L2 DQ8 (io) "Data I/O", L8 DQ23 (io) "Data I/O", M2 DQ9 (io) "Data I/O", M3 DQ10 (io) "Data I/O", M7 DQ21 (io) "Data I/O", M8 DQ22 (io) "Data I/O", N2 DQ12 (io) "Data I/O", N3 DQ11 (io) "Data I/O", N7 DQ20 (io) "Data I/O", N8 DQ19 (io) "Data I/O", P1 DQ13 (io) "Data I/O", P9 DQ18 (io) "Data I/O", R1 DQ14 (io) "Data I/O", R2 DQ15 (io) "Data I/O", R8 DQ16 (io) "Data I/O", R9 DQ17 (io) "Data I/O"
part B pins: A3 VSS (power) "Ground", A7 VDD (power) "Power", B2 VDD (power) "Power", B3 VSS (power) "Ground", B7 VDD (power) "Power", B8 VSS (power) "Ground", C1 VSS (power) "Ground", C9 VDD (power) "Power", D1 VSS (power) "Ground", D9 VDD (power) "Power", E1 VDD (power) "Power", E9 VSS (power) "Ground", F1 VSS (power) "Ground", F9 VDD (power) "Power", L1 VDD (power) "Power", L3 VSS (power) "Ground", L7 VDD (power) "Power", L9 VSS (power) "Ground", M1 VSS (power) "Ground", M9 VDD (power) "Power", N1 VSS (power) "Ground", N9 VDD (power) "Power", P2 VDD (power) "Power", P3 VSS (power) "Ground", P7 VDD (power) "Power", P8 VSS (power) "Ground", R3 VSS (power) "Ground", R7 VDD (power) "Power"

## IS61WV25632ALL-20BI-TR
designator U?
8 M High Speed Asynchronous CMOS SRAM with 3.3 V Supply, 256 K x 32, -40 to 85 degC, 90-Pin BGA (TF-BGA-90); Manufacturer: Integrated Silicon Solution Inc (ISSI); PartNumber: IS61WV25632ALL-20BI-TR; Density: 8M; Packing: Tape & Reel; Speed (ns): 20
footprint ISSI-TF-BGA-90-8000X13000DE (BGA, 90-Balls, Body 13x8mm, Pitch 0.8mm)
part A pins: A1 DQ1 (io) "Data I/O", A2 DQ0 (io) "Data I/O", A8 DQ31 (io) "Data I/O", A9 DQ30 (io) "Data I/O", B1 DQ2 (io) "Data I/O", B9 DQ29 (io) "Data I/O", C2 DQ3 (io) "Data I/O", C3 DQ4 (io) "Data I/O", C7 DQ27 (io) "Data I/O", C8 DQ28 (io) "Data I/O", D2 DQ6 (io) "Data I/O", D3 DQ5 (io) "Data I/O", D7 DQ26 (io) "Data I/O", D8 DQ25 (io) "Data I/O", E2 DQ7 (io) "Data I/O", E3 NC "No Connection", E7 NC "No Connection", E8 DQ24 (io) "Data I/O", F2 ~{BWa} (in) "Byte Write Control", F3 A3 (in) "Address Inputs", F7 A4 (in) "Address Inputs", F8 ~{BWd} (in) "Byte Write Control", G1 A0 (in) "Address Inputs", G2 A1 (in) "Address Inputs", G3 A2 (in) "Address Inputs", G7 A10 (in) "Address Inputs", G8 A5 (in) "Address Inputs", G9 A6 (in) "Address Inputs", H1 A15 (in) "Address Inputs", H2 A14 (in) "Address Inputs", H3 A13 (in) "Address Inputs", H7 A8 (in) "Address Inputs", H8 A7 (in) "Address Inputs", H9 A11 (in) "Address Inputs", J1 CE2 (in) "Chip Enable Input", J2 A17 (in) "Address Inputs", J3 A16 (in) "Address Inputs", J7 A9 (in) "Address Inputs", J8 A12 (in) "Address Inputs", J9 ~{CE} (in) "Chip Enable Input", K1 ~{BWb} (in) "Byte Write Control", K2 NC "No Connection", K3 NC "No Connection", K7 ~{OE} (in) "Output Enable Input", K8 ~{WE} (in) "Write Enable Input", K9 ~{BWc} (in) "Byte Write Control", L2 DQ8 (io) "Data I/O", L8 DQ23 (io) "Data I/O", M2 DQ9 (io) "Data I/O", M3 DQ10 (io) "Data I/O", M7 DQ21 (io) "Data I/O", M8 DQ22 (io) "Data I/O", N2 DQ12 (io) "Data I/O", N3 DQ11 (io) "Data I/O", N7 DQ20 (io) "Data I/O", N8 DQ19 (io) "Data I/O", P1 DQ13 (io) "Data I/O", P9 DQ18 (io) "Data I/O", R1 DQ14 (io) "Data I/O", R2 DQ15 (io) "Data I/O", R8 DQ16 (io) "Data I/O", R9 DQ17 (io) "Data I/O"
part B pins: A3 VSS (power) "Ground", A7 VDD (power) "Power", B2 VDD (power) "Power", B3 VSS (power) "Ground", B7 VDD (power) "Power", B8 VSS (power) "Ground", C1 VSS (power) "Ground", C9 VDD (power) "Power", D1 VSS (power) "Ground", D9 VDD (power) "Power", E1 VDD (power) "Power", E9 VSS (power) "Ground", F1 VSS (power) "Ground", F9 VDD (power) "Power", L1 VDD (power) "Power", L3 VSS (power) "Ground", L7 VDD (power) "Power", L9 VSS (power) "Ground", M1 VSS (power) "Ground", M9 VDD (power) "Power", N1 VSS (power) "Ground", N9 VDD (power) "Power", P2 VDD (power) "Power", P3 VSS (power) "Ground", P7 VDD (power) "Power", P8 VSS (power) "Ground", R3 VSS (power) "Ground", R7 VDD (power) "Power"

## IS61WV25632BLL-10BI
designator U?
8 M High Speed Asynchronous CMOS SRAM with 3.3 V Supply, 256 K x 32, -40 to 85 degC, 90-Pin BGA (TF-BGA-90); Manufacturer: Integrated Silicon Solution Inc (ISSI); PartNumber: IS61WV25632BLL-10BI; Density: 8M; Packing: Tray / Tube; Speed (ns): 10
footprint ISSI-TF-BGA-90-8000X13000DE (BGA, 90-Balls, Body 13x8mm, Pitch 0.8mm)
part A pins: A1 DQ1 (io) "Data I/O", A2 DQ0 (io) "Data I/O", A8 DQ31 (io) "Data I/O", A9 DQ30 (io) "Data I/O", B1 DQ2 (io) "Data I/O", B9 DQ29 (io) "Data I/O", C2 DQ3 (io) "Data I/O", C3 DQ4 (io) "Data I/O", C7 DQ27 (io) "Data I/O", C8 DQ28 (io) "Data I/O", D2 DQ6 (io) "Data I/O", D3 DQ5 (io) "Data I/O", D7 DQ26 (io) "Data I/O", D8 DQ25 (io) "Data I/O", E2 DQ7 (io) "Data I/O", E3 NC "No Connection", E7 NC "No Connection", E8 DQ24 (io) "Data I/O", F2 ~{BWa} (in) "Byte Write Control", F3 A3 (in) "Address Inputs", F7 A4 (in) "Address Inputs", F8 ~{BWd} (in) "Byte Write Control", G1 A0 (in) "Address Inputs", G2 A1 (in) "Address Inputs", G3 A2 (in) "Address Inputs", G7 A10 (in) "Address Inputs", G8 A5 (in) "Address Inputs", G9 A6 (in) "Address Inputs", H1 A15 (in) "Address Inputs", H2 A14 (in) "Address Inputs", H3 A13 (in) "Address Inputs", H7 A8 (in) "Address Inputs", H8 A7 (in) "Address Inputs", H9 A11 (in) "Address Inputs", J1 CE2 (in) "Chip Enable Input", J2 A17 (in) "Address Inputs", J3 A16 (in) "Address Inputs", J7 A9 (in) "Address Inputs", J8 A12 (in) "Address Inputs", J9 ~{CE} (in) "Chip Enable Input", K1 ~{BWb} (in) "Byte Write Control", K2 NC "No Connection", K3 NC "No Connection", K7 ~{OE} (in) "Output Enable Input", K8 ~{WE} (in) "Write Enable Input", K9 ~{BWc} (in) "Byte Write Control", L2 DQ8 (io) "Data I/O", L8 DQ23 (io) "Data I/O", M2 DQ9 (io) "Data I/O", M3 DQ10 (io) "Data I/O", M7 DQ21 (io) "Data I/O", M8 DQ22 (io) "Data I/O", N2 DQ12 (io) "Data I/O", N3 DQ11 (io) "Data I/O", N7 DQ20 (io) "Data I/O", N8 DQ19 (io) "Data I/O", P1 DQ13 (io) "Data I/O", P9 DQ18 (io) "Data I/O", R1 DQ14 (io) "Data I/O", R2 DQ15 (io) "Data I/O", R8 DQ16 (io) "Data I/O", R9 DQ17 (io) "Data I/O"
part B pins: A3 VSS (power) "Ground", A7 VDD (power) "Power", B2 VDD (power) "Power", B3 VSS (power) "Ground", B7 VDD (power) "Power", B8 VSS (power) "Ground", C1 VSS (power) "Ground", C9 VDD (power) "Power", D1 VSS (power) "Ground", D9 VDD (power) "Power", E1 VDD (power) "Power", E9 VSS (power) "Ground", F1 VSS (power) "Ground", F9 VDD (power) "Power", L1 VDD (power) "Power", L3 VSS (power) "Ground", L7 VDD (power) "Power", L9 VSS (power) "Ground", M1 VSS (power) "Ground", M9 VDD (power) "Power", N1 VSS (power) "Ground", N9 VDD (power) "Power", P2 VDD (power) "Power", P3 VSS (power) "Ground", P7 VDD (power) "Power", P8 VSS (power) "Ground", R3 VSS (power) "Ground", R7 VDD (power) "Power"

## IS61WV25632BLL-10BI-TR
designator U?
8 M High Speed Asynchronous CMOS SRAM with 3.3 V Supply, 256 K x 32, -40 to 85 degC, 90-Pin BGA (TF-BGA-90); Manufacturer: Integrated Silicon Solution Inc (ISSI); PartNumber: IS61WV25632BLL-10BI-TR; Density: 8M; Packing: Tape & Reel; Speed (ns): 10
footprint ISSI-TF-BGA-90-8000X13000DE (BGA, 90-Balls, Body 13x8mm, Pitch 0.8mm)
part A pins: A1 DQ1 (io) "Data I/O", A2 DQ0 (io) "Data I/O", A8 DQ31 (io) "Data I/O", A9 DQ30 (io) "Data I/O", B1 DQ2 (io) "Data I/O", B9 DQ29 (io) "Data I/O", C2 DQ3 (io) "Data I/O", C3 DQ4 (io) "Data I/O", C7 DQ27 (io) "Data I/O", C8 DQ28 (io) "Data I/O", D2 DQ6 (io) "Data I/O", D3 DQ5 (io) "Data I/O", D7 DQ26 (io) "Data I/O", D8 DQ25 (io) "Data I/O", E2 DQ7 (io) "Data I/O", E3 NC "No Connection", E7 NC "No Connection", E8 DQ24 (io) "Data I/O", F2 ~{BWa} (in) "Byte Write Control", F3 A3 (in) "Address Inputs", F7 A4 (in) "Address Inputs", F8 ~{BWd} (in) "Byte Write Control", G1 A0 (in) "Address Inputs", G2 A1 (in) "Address Inputs", G3 A2 (in) "Address Inputs", G7 A10 (in) "Address Inputs", G8 A5 (in) "Address Inputs", G9 A6 (in) "Address Inputs", H1 A15 (in) "Address Inputs", H2 A14 (in) "Address Inputs", H3 A13 (in) "Address Inputs", H7 A8 (in) "Address Inputs", H8 A7 (in) "Address Inputs", H9 A11 (in) "Address Inputs", J1 CE2 (in) "Chip Enable Input", J2 A17 (in) "Address Inputs", J3 A16 (in) "Address Inputs", J7 A9 (in) "Address Inputs", J8 A12 (in) "Address Inputs", J9 ~{CE} (in) "Chip Enable Input", K1 ~{BWb} (in) "Byte Write Control", K2 NC "No Connection", K3 NC "No Connection", K7 ~{OE} (in) "Output Enable Input", K8 ~{WE} (in) "Write Enable Input", K9 ~{BWc} (in) "Byte Write Control", L2 DQ8 (io) "Data I/O", L8 DQ23 (io) "Data I/O", M2 DQ9 (io) "Data I/O", M3 DQ10 (io) "Data I/O", M7 DQ21 (io) "Data I/O", M8 DQ22 (io) "Data I/O", N2 DQ12 (io) "Data I/O", N3 DQ11 (io) "Data I/O", N7 DQ20 (io) "Data I/O", N8 DQ19 (io) "Data I/O", P1 DQ13 (io) "Data I/O", P9 DQ18 (io) "Data I/O", R1 DQ14 (io) "Data I/O", R2 DQ15 (io) "Data I/O", R8 DQ16 (io) "Data I/O", R9 DQ17 (io) "Data I/O"
part B pins: A3 VSS (power) "Ground", A7 VDD (power) "Power", B2 VDD (power) "Power", B3 VSS (power) "Ground", B7 VDD (power) "Power", B8 VSS (power) "Ground", C1 VSS (power) "Ground", C9 VDD (power) "Power", D1 VSS (power) "Ground", D9 VDD (power) "Power", E1 VDD (power) "Power", E9 VSS (power) "Ground", F1 VSS (power) "Ground", F9 VDD (power) "Power", L1 VDD (power) "Power", L3 VSS (power) "Ground", L7 VDD (power) "Power", L9 VSS (power) "Ground", M1 VSS (power) "Ground", M9 VDD (power) "Power", N1 VSS (power) "Ground", N9 VDD (power) "Power", P2 VDD (power) "Power", P3 VSS (power) "Ground", P7 VDD (power) "Power", P8 VSS (power) "Ground", R3 VSS (power) "Ground", R7 VDD (power) "Power"

## IS61WV25632BLL-10BLI
designator U?
8 M High Speed Asynchronous CMOS SRAM with 3.3 V Supply, 256 K x 32, -40 to 85 degC, 90-Pin BGA (TF-BGA-90), Pb-Free; Manufacturer: Integrated Silicon Solution Inc (ISSI); PartNumber: IS61WV25632BLL-10BLI; Density: 8M; Packing: Tray / Tube; Speed (ns): 10
footprint ISSI-TF-BGA-90-8000X13000DE (BGA, 90-Balls, Body 13x8mm, Pitch 0.8mm)
part A pins: A1 DQ1 (io) "Data I/O", A2 DQ0 (io) "Data I/O", A8 DQ31 (io) "Data I/O", A9 DQ30 (io) "Data I/O", B1 DQ2 (io) "Data I/O", B9 DQ29 (io) "Data I/O", C2 DQ3 (io) "Data I/O", C3 DQ4 (io) "Data I/O", C7 DQ27 (io) "Data I/O", C8 DQ28 (io) "Data I/O", D2 DQ6 (io) "Data I/O", D3 DQ5 (io) "Data I/O", D7 DQ26 (io) "Data I/O", D8 DQ25 (io) "Data I/O", E2 DQ7 (io) "Data I/O", E3 NC "No Connection", E7 NC "No Connection", E8 DQ24 (io) "Data I/O", F2 ~{BWa} (in) "Byte Write Control", F3 A3 (in) "Address Inputs", F7 A4 (in) "Address Inputs", F8 ~{BWd} (in) "Byte Write Control", G1 A0 (in) "Address Inputs", G2 A1 (in) "Address Inputs", G3 A2 (in) "Address Inputs", G7 A10 (in) "Address Inputs", G8 A5 (in) "Address Inputs", G9 A6 (in) "Address Inputs", H1 A15 (in) "Address Inputs", H2 A14 (in) "Address Inputs", H3 A13 (in) "Address Inputs", H7 A8 (in) "Address Inputs", H8 A7 (in) "Address Inputs", H9 A11 (in) "Address Inputs", J1 CE2 (in) "Chip Enable Input", J2 A17 (in) "Address Inputs", J3 A16 (in) "Address Inputs", J7 A9 (in) "Address Inputs", J8 A12 (in) "Address Inputs", J9 ~{CE} (in) "Chip Enable Input", K1 ~{BWb} (in) "Byte Write Control", K2 NC "No Connection", K3 NC "No Connection", K7 ~{OE} (in) "Output Enable Input", K8 ~{WE} (in) "Write Enable Input", K9 ~{BWc} (in) "Byte Write Control", L2 DQ8 (io) "Data I/O", L8 DQ23 (io) "Data I/O", M2 DQ9 (io) "Data I/O", M3 DQ10 (io) "Data I/O", M7 DQ21 (io) "Data I/O", M8 DQ22 (io) "Data I/O", N2 DQ12 (io) "Data I/O", N3 DQ11 (io) "Data I/O", N7 DQ20 (io) "Data I/O", N8 DQ19 (io) "Data I/O", P1 DQ13 (io) "Data I/O", P9 DQ18 (io) "Data I/O", R1 DQ14 (io) "Data I/O", R2 DQ15 (io) "Data I/O", R8 DQ16 (io) "Data I/O", R9 DQ17 (io) "Data I/O"
part B pins: A3 VSS (power) "Ground", A7 VDD (power) "Power", B2 VDD (power) "Power", B3 VSS (power) "Ground", B7 VDD (power) "Power", B8 VSS (power) "Ground", C1 VSS (power) "Ground", C9 VDD (power) "Power", D1 VSS (power) "Ground", D9 VDD (power) "Power", E1 VDD (power) "Power", E9 VSS (power) "Ground", F1 VSS (power) "Ground", F9 VDD (power) "Power", L1 VDD (power) "Power", L3 VSS (power) "Ground", L7 VDD (power) "Power", L9 VSS (power) "Ground", M1 VSS (power) "Ground", M9 VDD (power) "Power", N1 VSS (power) "Ground", N9 VDD (power) "Power", P2 VDD (power) "Power", P3 VSS (power) "Ground", P7 VDD (power) "Power", P8 VSS (power) "Ground", R3 VSS (power) "Ground", R7 VDD (power) "Power"

## IS61WV25632BLL-10BLI-TR
designator U?
8 M High Speed Asynchronous CMOS SRAM with 3.3 V Supply, 256 K x 32, -40 to 85 degC, 90-Pin BGA (TF-BGA-90), Pb-Free; Manufacturer: Integrated Silicon Solution Inc (ISSI); PartNumber: IS61WV25632BLL-10BLI-TR; Density: 8M; Packing: Tape & Reel; Speed (ns): 10
footprint ISSI-TF-BGA-90-8000X13000DE (BGA, 90-Balls, Body 13x8mm, Pitch 0.8mm)
part A pins: A1 DQ1 (io) "Data I/O", A2 DQ0 (io) "Data I/O", A8 DQ31 (io) "Data I/O", A9 DQ30 (io) "Data I/O", B1 DQ2 (io) "Data I/O", B9 DQ29 (io) "Data I/O", C2 DQ3 (io) "Data I/O", C3 DQ4 (io) "Data I/O", C7 DQ27 (io) "Data I/O", C8 DQ28 (io) "Data I/O", D2 DQ6 (io) "Data I/O", D3 DQ5 (io) "Data I/O", D7 DQ26 (io) "Data I/O", D8 DQ25 (io) "Data I/O", E2 DQ7 (io) "Data I/O", E3 NC "No Connection", E7 NC "No Connection", E8 DQ24 (io) "Data I/O", F2 ~{BWa} (in) "Byte Write Control", F3 A3 (in) "Address Inputs", F7 A4 (in) "Address Inputs", F8 ~{BWd} (in) "Byte Write Control", G1 A0 (in) "Address Inputs", G2 A1 (in) "Address Inputs", G3 A2 (in) "Address Inputs", G7 A10 (in) "Address Inputs", G8 A5 (in) "Address Inputs", G9 A6 (in) "Address Inputs", H1 A15 (in) "Address Inputs", H2 A14 (in) "Address Inputs", H3 A13 (in) "Address Inputs", H7 A8 (in) "Address Inputs", H8 A7 (in) "Address Inputs", H9 A11 (in) "Address Inputs", J1 CE2 (in) "Chip Enable Input", J2 A17 (in) "Address Inputs", J3 A16 (in) "Address Inputs", J7 A9 (in) "Address Inputs", J8 A12 (in) "Address Inputs", J9 ~{CE} (in) "Chip Enable Input", K1 ~{BWb} (in) "Byte Write Control", K2 NC "No Connection", K3 NC "No Connection", K7 ~{OE} (in) "Output Enable Input", K8 ~{WE} (in) "Write Enable Input", K9 ~{BWc} (in) "Byte Write Control", L2 DQ8 (io) "Data I/O", L8 DQ23 (io) "Data I/O", M2 DQ9 (io) "Data I/O", M3 DQ10 (io) "Data I/O", M7 DQ21 (io) "Data I/O", M8 DQ22 (io) "Data I/O", N2 DQ12 (io) "Data I/O", N3 DQ11 (io) "Data I/O", N7 DQ20 (io) "Data I/O", N8 DQ19 (io) "Data I/O", P1 DQ13 (io) "Data I/O", P9 DQ18 (io) "Data I/O", R1 DQ14 (io) "Data I/O", R2 DQ15 (io) "Data I/O", R8 DQ16 (io) "Data I/O", R9 DQ17 (io) "Data I/O"
part B pins: A3 VSS (power) "Ground", A7 VDD (power) "Power", B2 VDD (power) "Power", B3 VSS (power) "Ground", B7 VDD (power) "Power", B8 VSS (power) "Ground", C1 VSS (power) "Ground", C9 VDD (power) "Power", D1 VSS (power) "Ground", D9 VDD (power) "Power", E1 VDD (power) "Power", E9 VSS (power) "Ground", F1 VSS (power) "Ground", F9 VDD (power) "Power", L1 VDD (power) "Power", L3 VSS (power) "Ground", L7 VDD (power) "Power", L9 VSS (power) "Ground", M1 VSS (power) "Ground", M9 VDD (power) "Power", N1 VSS (power) "Ground", N9 VDD (power) "Power", P2 VDD (power) "Power", P3 VSS (power) "Ground", P7 VDD (power) "Power", P8 VSS (power) "Ground", R3 VSS (power) "Ground", R7 VDD (power) "Power"

## IS61WV51216ALL-20MI
designator U?
8 M High Speed Asynchronous CMOS SRAM with 3.3 V Supply, 512 K x 16, -40 to 85 degC, 48-Pin BGA (TF-BGA-48); Manufacturer: Integrated Silicon Solution Inc (ISSI); PartNumber: IS61WV51216ALL-20MI; Density: 8M; Packing: Tray / Tube; Speed (ns): 20
footprint ISSI-TF-BGA-48-9000x11000DE (BGA, 48-Balls, Body 11x9mm, Pitch 0.75mm)
pins: A1 ~{LB} (in) "Lower-byte Control (I/O0-I/O7)", A2 ~{OE} (in) "Output Enable Input", A3 A0 (in) "Address Input", A4 A1 (in) "Address Input", A5 A2 (in) "Address Input", A6 NC "No Connection", B1 I/O8 (io) "Data Input/Output", B2 ~{UB} (in) "Upper-byte Control (I/O8-I/O15)", B3 A3 (in) "Address Input", B4 A4 (in) "Address Input", B5 ~{CE} (in) "Chip Enable Input", B6 I/O0 (io) "Data Input/Output", C1 I/O9 (io) "Data Input/Output", C2 I/O10 (io) "Data Input/Output", C3 A5 (in) "Address Input", C4 A6 (in) "Address Input", C5 I/O1 (io) "Data Input/Output", C6 I/O2 (io) "Data Input/Output", D1 GND (power) "Ground", D2 I/O11 (io) "Data Input/Output", D3 A17 (in) "Address Input", D4 A7 (in) "Address Input", D5 I/O3 (io) "Data Input/Output", D6 VDD (power) "Power", E1 VDD (power) "Power", E2 I/O12 (io) "Data Input/Output", E3 NC "No Connection", E4 A16 (in) "Address Input", E5 I/O4 (io) "Data Input/Output", E6 GND (power) "Ground", F1 I/O14 (io) "Data Input/Output", F2 I/O13 (io) "Data Input/Output", F3 A14 (in) "Address Input", F4 A15 (in) "Address Input", F5 I/O5 (io) "Data Input/Output", F6 I/O6 (io) "Data Input/Output", G1 I/O15 (io) "Data Input/Output", G2 NC "No Connection", G3 A12 (in) "Address Input", G4 A13 (in) "Address Input", G5 ~{WE} (in) "Write Enable Input", G6 I/O7 (io) "Data Input/Output", H1 A18 (in) "Address Input", H2 A8 (in) "Address Input", H3 A9 (in) "Address Input", H4 A10 (in) "Address Input", H5 A11 (in) "Address Input", H6 NC "No Connection"

## IS61WV51216ALL-20MI-TR
designator U?
8 M High Speed Asynchronous CMOS SRAM with 3.3 V Supply, 512 K x 16, -40 to 85 degC, 48-Pin BGA (TF-BGA-48); Manufacturer: Integrated Silicon Solution Inc (ISSI); PartNumber: IS61WV51216ALL-20MI-TR; Density: 8M; Packing: Tape & Reel; Speed (ns): 20
footprint ISSI-TF-BGA-48-9000x11000DE (BGA, 48-Balls, Body 11x9mm, Pitch 0.75mm)
pins: A1 ~{LB} (in) "Lower-byte Control (I/O0-I/O7)", A2 ~{OE} (in) "Output Enable Input", A3 A0 (in) "Address Input", A4 A1 (in) "Address Input", A5 A2 (in) "Address Input", A6 NC "No Connection", B1 I/O8 (io) "Data Input/Output", B2 ~{UB} (in) "Upper-byte Control (I/O8-I/O15)", B3 A3 (in) "Address Input", B4 A4 (in) "Address Input", B5 ~{CE} (in) "Chip Enable Input", B6 I/O0 (io) "Data Input/Output", C1 I/O9 (io) "Data Input/Output", C2 I/O10 (io) "Data Input/Output", C3 A5 (in) "Address Input", C4 A6 (in) "Address Input", C5 I/O1 (io) "Data Input/Output", C6 I/O2 (io) "Data Input/Output", D1 GND (power) "Ground", D2 I/O11 (io) "Data Input/Output", D3 A17 (in) "Address Input", D4 A7 (in) "Address Input", D5 I/O3 (io) "Data Input/Output", D6 VDD (power) "Power", E1 VDD (power) "Power", E2 I/O12 (io) "Data Input/Output", E3 NC "No Connection", E4 A16 (in) "Address Input", E5 I/O4 (io) "Data Input/Output", E6 GND (power) "Ground", F1 I/O14 (io) "Data Input/Output", F2 I/O13 (io) "Data Input/Output", F3 A14 (in) "Address Input", F4 A15 (in) "Address Input", F5 I/O5 (io) "Data Input/Output", F6 I/O6 (io) "Data Input/Output", G1 I/O15 (io) "Data Input/Output", G2 NC "No Connection", G3 A12 (in) "Address Input", G4 A13 (in) "Address Input", G5 ~{WE} (in) "Write Enable Input", G6 I/O7 (io) "Data Input/Output", H1 A18 (in) "Address Input", H2 A8 (in) "Address Input", H3 A9 (in) "Address Input", H4 A10 (in) "Address Input", H5 A11 (in) "Address Input", H6 NC "No Connection"

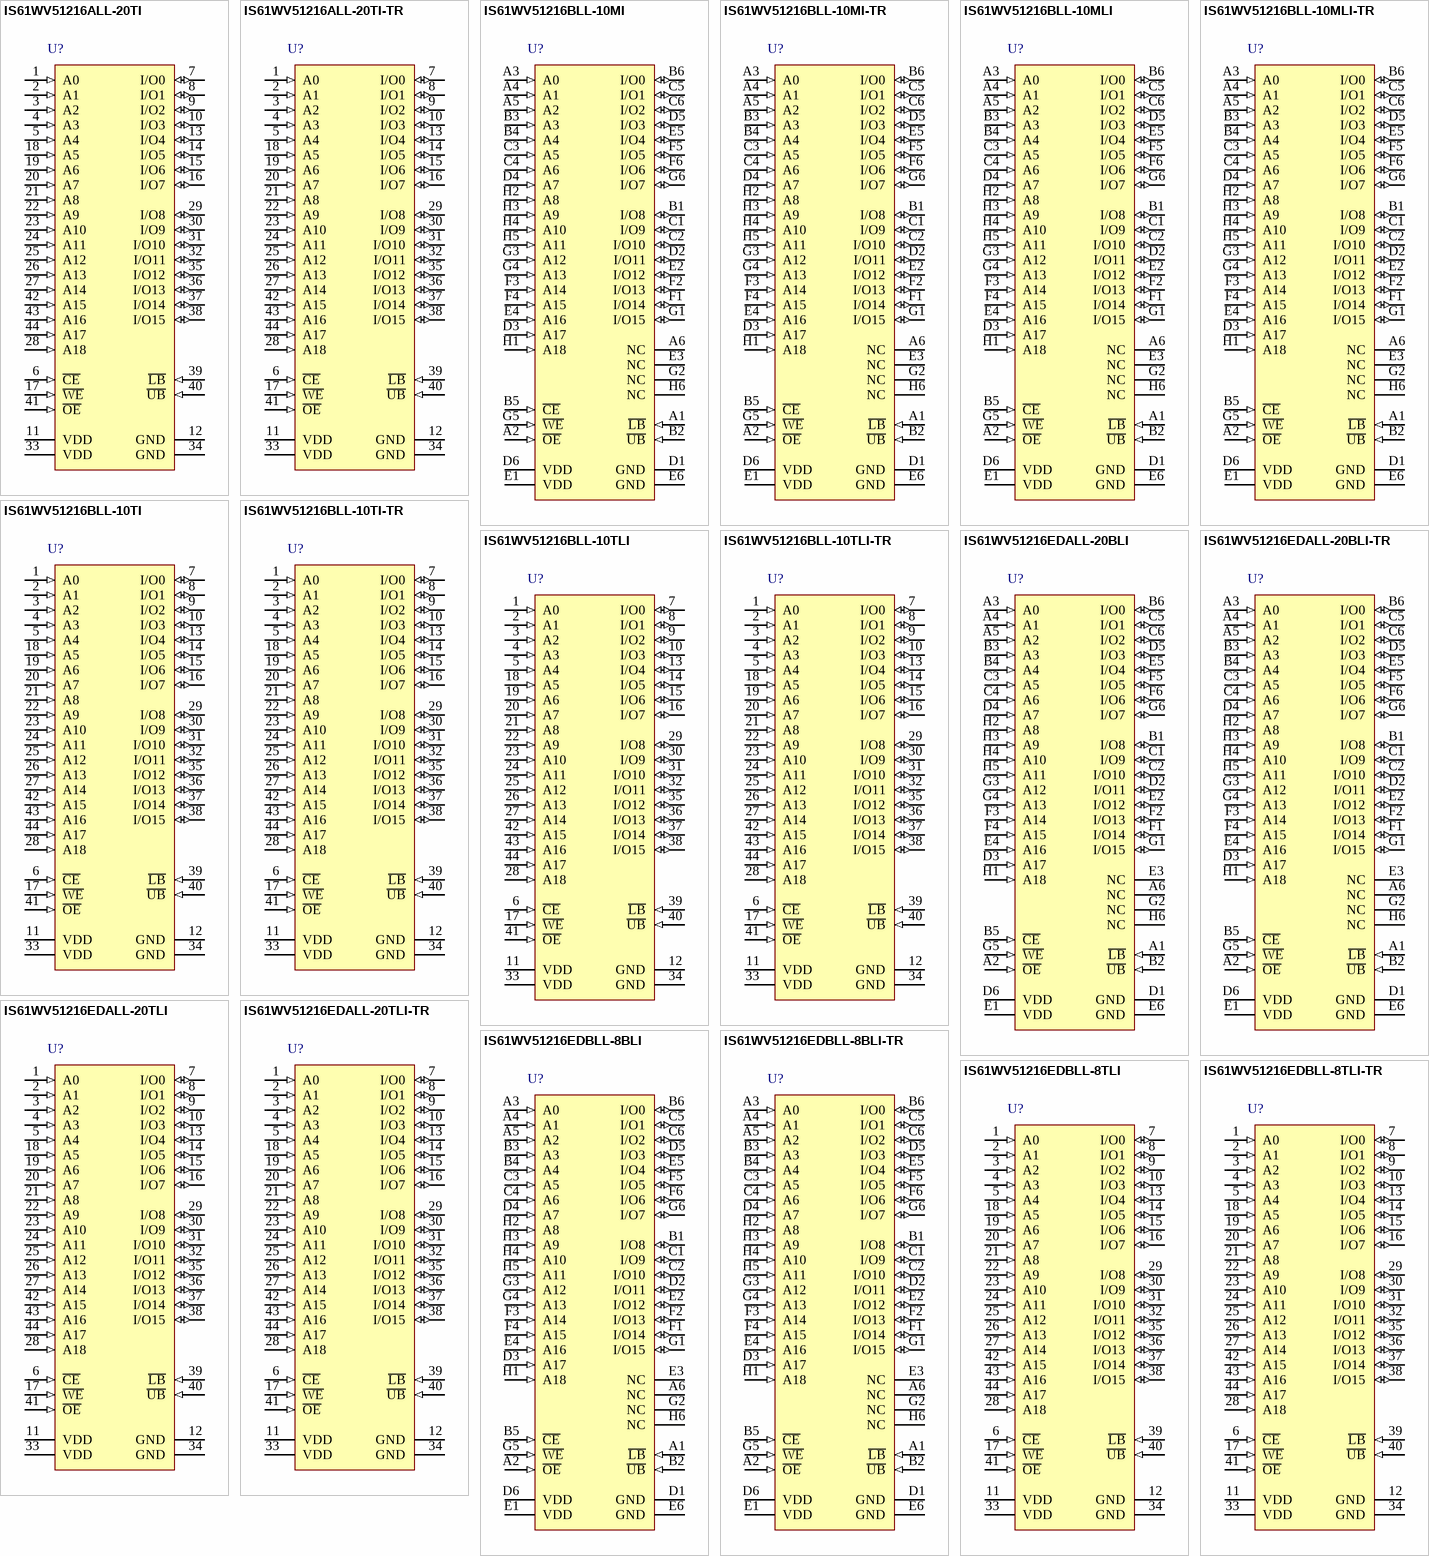
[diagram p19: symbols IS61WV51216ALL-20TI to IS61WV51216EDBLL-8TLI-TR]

## IS61WV51216ALL-20TI
designator U?
8 M High Speed Asynchronous CMOS SRAM with 3.3 V Supply, 512 K x 16, -40 to 85 degC, 44-Pin SOP (TSOP-2-44); Manufacturer: Integrated Silicon Solution Inc (ISSI); PartNumber: IS61WV51216ALL-20TI; Density: 8M; Packing: Tray / Tube; Speed (ns): 20
footprint ISSI-TSOP-2-44_N (SOP, 44-Leads, Body 18.5x10.3mm, Pitch 0.8mm, IPC Medium Density)
pins: 1 A0 (in) "Address Input", 2 A1 (in) "Address Input", 3 A2 (in) "Address Input", 4 A3 (in) "Address Input", 5 A4 (in) "Address Input", 6 ~{CE} (in) "Chip Enable Input", 7 I/O0 (io) "Data Input/Output", 8 I/O1 (io) "Data Input/Output", 9 I/O2 (io) "Data Input/Output", 10 I/O3 (io) "Data Input/Output", 11 VDD (power) "Power", 12 GND (power) "Ground", 13 I/O4 (io) "Data Input/Output", 14 I/O5 (io) "Data Input/Output", 15 I/O6 (io) "Data Input/Output", 16 I/O7 (io) "Data Input/Output", 17 ~{WE} (in) "Write Enable Input", 18 A5 (in) "Address Input", 19 A6 (in) "Address Input", 20 A7 (in) "Address Input", 21 A8 (in) "Address Input", 22 A9 (in) "Address Input", 23 A10 (in) "Address Input", 24 A11 (in) "Address Input", 25 A12 (in) "Address Input", 26 A13 (in) "Address Input", 27 A14 (in) "Address Input", 28 A18 (in) "Address Input", 29 I/O8 (io) "Data Input/Output", 30 I/O9 (io) "Data Input/Output", 31 I/O10 (io) "Data Input/Output", 32 I/O11 (io) "Data Input/Output", 33 VDD (power) "Power", 34 GND (power) "Ground", 35 I/O12 (io) "Data Input/Output", 36 I/O13 (io) "Data Input/Output", 37 I/O14 (io) "Data Input/Output", 38 I/O15 (io) "Data Input/Output", 39 ~{LB} (in) "Lower-byte Control (I/O0-I/O7)", 40 ~{UB} (in) "Upper-byte Control (I/O8-I/O15)", 41 ~{OE} (in) "Output Enable Input", 42 A15 (in) "Address Input", 43 A16 (in) "Address Input", 44 A17 (in) "Address Input"

## IS61WV51216ALL-20TI-TR
designator U?
8 M High Speed Asynchronous CMOS SRAM with 3.3 V Supply, 512 K x 16, -40 to 85 degC, 44-Pin SOP (TSOP-2-44); Manufacturer: Integrated Silicon Solution Inc (ISSI); PartNumber: IS61WV51216ALL-20TI-TR; Density: 8M; Packing: Tape & Reel; Speed (ns): 20
footprint ISSI-TSOP-2-44_N (SOP, 44-Leads, Body 18.5x10.3mm, Pitch 0.8mm, IPC Medium Density)
pins: 1 A0 (in) "Address Input", 2 A1 (in) "Address Input", 3 A2 (in) "Address Input", 4 A3 (in) "Address Input", 5 A4 (in) "Address Input", 6 ~{CE} (in) "Chip Enable Input", 7 I/O0 (io) "Data Input/Output", 8 I/O1 (io) "Data Input/Output", 9 I/O2 (io) "Data Input/Output", 10 I/O3 (io) "Data Input/Output", 11 VDD (power) "Power", 12 GND (power) "Ground", 13 I/O4 (io) "Data Input/Output", 14 I/O5 (io) "Data Input/Output", 15 I/O6 (io) "Data Input/Output", 16 I/O7 (io) "Data Input/Output", 17 ~{WE} (in) "Write Enable Input", 18 A5 (in) "Address Input", 19 A6 (in) "Address Input", 20 A7 (in) "Address Input", 21 A8 (in) "Address Input", 22 A9 (in) "Address Input", 23 A10 (in) "Address Input", 24 A11 (in) "Address Input", 25 A12 (in) "Address Input", 26 A13 (in) "Address Input", 27 A14 (in) "Address Input", 28 A18 (in) "Address Input", 29 I/O8 (io) "Data Input/Output", 30 I/O9 (io) "Data Input/Output", 31 I/O10 (io) "Data Input/Output", 32 I/O11 (io) "Data Input/Output", 33 VDD (power) "Power", 34 GND (power) "Ground", 35 I/O12 (io) "Data Input/Output", 36 I/O13 (io) "Data Input/Output", 37 I/O14 (io) "Data Input/Output", 38 I/O15 (io) "Data Input/Output", 39 ~{LB} (in) "Lower-byte Control (I/O0-I/O7)", 40 ~{UB} (in) "Upper-byte Control (I/O8-I/O15)", 41 ~{OE} (in) "Output Enable Input", 42 A15 (in) "Address Input", 43 A16 (in) "Address Input", 44 A17 (in) "Address Input"

## IS61WV51216BLL-10MI
designator U?
8 M High Speed Asynchronous CMOS SRAM with 3.3 V Supply, 512 K x 16, -40 to 85 degC, 48-Pin BGA (TF-BGA-48); Manufacturer: Integrated Silicon Solution Inc (ISSI); PartNumber: IS61WV51216BLL-10MI; Density: 8M; Packing: Tray / Tube; Speed (ns): 10
footprint ISSI-TF-BGA-48-9000x11000DE (BGA, 48-Balls, Body 11x9mm, Pitch 0.75mm)
pins: A1 ~{LB} (in) "Lower-byte Control (I/O0-I/O7)", A2 ~{OE} (in) "Output Enable Input", A3 A0 (in) "Address Input", A4 A1 (in) "Address Input", A5 A2 (in) "Address Input", A6 NC "No Connection", B1 I/O8 (io) "Data Input/Output", B2 ~{UB} (in) "Upper-byte Control (I/O8-I/O15)", B3 A3 (in) "Address Input", B4 A4 (in) "Address Input", B5 ~{CE} (in) "Chip Enable Input", B6 I/O0 (io) "Data Input/Output", C1 I/O9 (io) "Data Input/Output", C2 I/O10 (io) "Data Input/Output", C3 A5 (in) "Address Input", C4 A6 (in) "Address Input", C5 I/O1 (io) "Data Input/Output", C6 I/O2 (io) "Data Input/Output", D1 GND (power) "Ground", D2 I/O11 (io) "Data Input/Output", D3 A17 (in) "Address Input", D4 A7 (in) "Address Input", D5 I/O3 (io) "Data Input/Output", D6 VDD (power) "Power", E1 VDD (power) "Power", E2 I/O12 (io) "Data Input/Output", E3 NC "No Connection", E4 A16 (in) "Address Input", E5 I/O4 (io) "Data Input/Output", E6 GND (power) "Ground", F1 I/O14 (io) "Data Input/Output", F2 I/O13 (io) "Data Input/Output", F3 A14 (in) "Address Input", F4 A15 (in) "Address Input", F5 I/O5 (io) "Data Input/Output", F6 I/O6 (io) "Data Input/Output", G1 I/O15 (io) "Data Input/Output", G2 NC "No Connection", G3 A12 (in) "Address Input", G4 A13 (in) "Address Input", G5 ~{WE} (in) "Write Enable Input", G6 I/O7 (io) "Data Input/Output", H1 A18 (in) "Address Input", H2 A8 (in) "Address Input", H3 A9 (in) "Address Input", H4 A10 (in) "Address Input", H5 A11 (in) "Address Input", H6 NC "No Connection"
